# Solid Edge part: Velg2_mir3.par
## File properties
Author: KULL
Template: Iso Metric Part.par
Last saved by: KULL
Revision: 2
Application: Solid Edge
Accuracy: 0,990
Username: KULL
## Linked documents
Velg2.par
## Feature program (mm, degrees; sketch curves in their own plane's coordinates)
part copy "CopiedPart_1"
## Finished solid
Body 1: solid body, 389 faces, 931 edges, 512 vertices.
  Faces by surface: blend 256, torus 63, swept 32, cylinder 24, cone 10, plane 2, spun 2
  Edges by curve: intersection 512, circle 403, line 16
Bounding box of the edges (mm; curved faces can reach further): 43.118 x 87.299 x 87.299, from (-41.1766, -43.6493, -43.6493) to (1.9413, 43.6493, 43.6493).
Cylindrical faces by radius (mm): R4 x1, R8 x1, R10 x1, R36.3826 x1, R38.3116 x17, R38.3826 x1, R40.3116 x2
Conical faces (half-angle, radius in mm at the cone's reference point): 14.1898 deg R43.1591 x1, 14.1898 deg R43.6493 x1, 17.3646 deg R36.5649 x1, 17.3646 deg R38.1293 x1, 17.3646 deg R38.5649 x1, 17.3646 deg R40.1293 x1, 75.8102 deg R41.0291 x1, 75.8102 deg R41.5194 x1, 75.8102 deg R43.1591 x1, 75.8102 deg R43.6493 x1
Toroidal faces (ring radius, tube radius in mm): R8.1 r0.1 x1, R13 r3 x1, R34.3116 r4 x17, R36.3116 r4 x2, R36.7771 r0.6 x16, R38.0022 r0.6 x16, R40.3826 r4 x2, R41.9116 r1.6 x2, R41.9116 r3.6 x2, R42.3826 r4 x2, R43.0142 r0.2 x2
Planar faces by outward normal: +x 1, -x 1
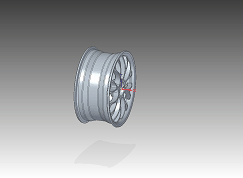
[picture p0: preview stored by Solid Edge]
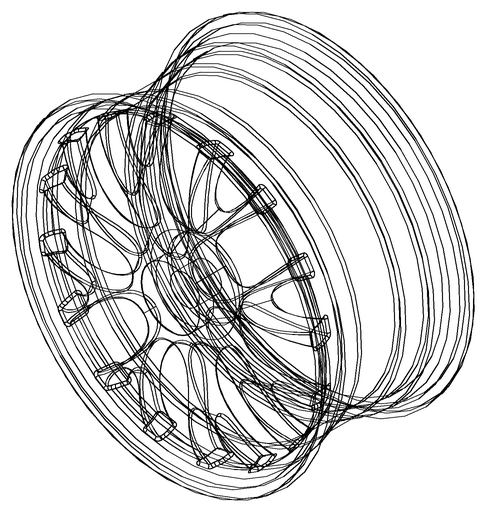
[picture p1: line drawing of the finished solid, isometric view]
